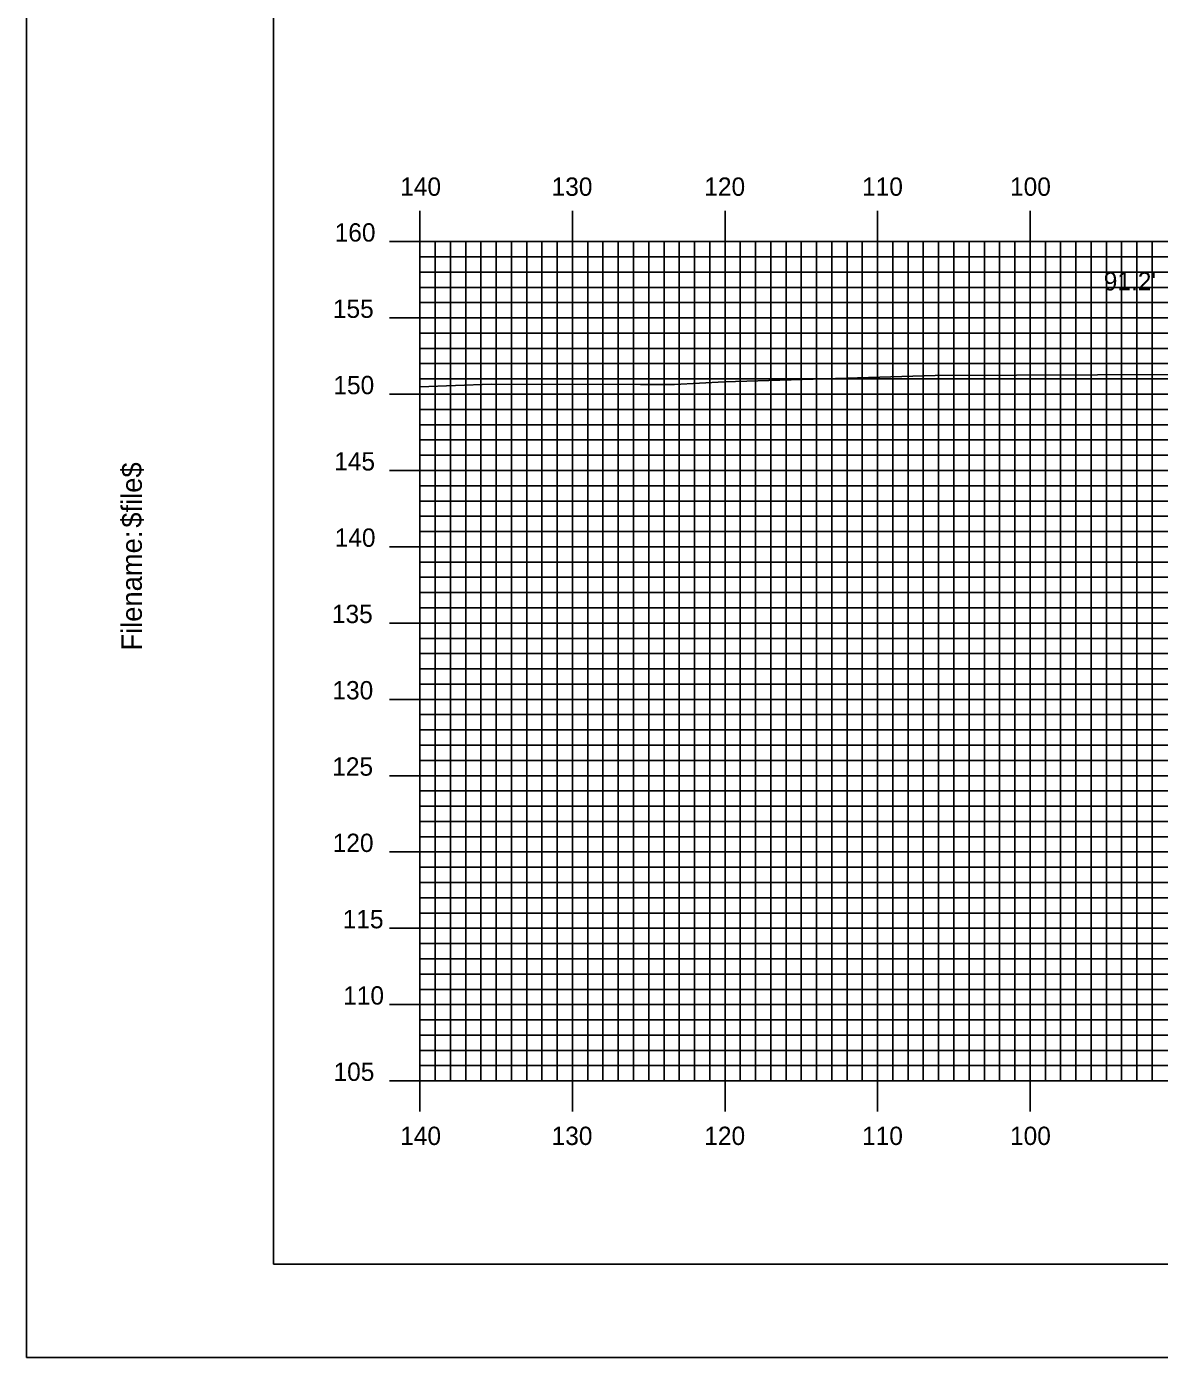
# Model space of a CAD drawing. Extents: x 1770055 to 1770398, y 442591 to 442811.
# Drawn here: x 1770054.7 to 1770129, y 442590.5 to 442677.8 of the extents above; entities that cross this region are included whole.
import ezdxf

# ---------------------------------------------------------------- set-up
doc = ezdxf.new("R2010")
doc.units = 0
for name, color, linetype in [('BORDER', 7, 'Continuous'), ('D_Text_Standard', 7, 'Continuous'), ('H_V ANNOTATION', 7, 'Continuous'), ('MAJOR', 7, 'Continuous'), ('MINOR', 7, 'Continuous'), ('PLOT BOUNDARY', 7, 'Continuous'), ('S_Roadway_Centerline', 7, 'Continuous')]:
    doc.layers.add(name, color=color, linetype=linetype)

msp = doc.modelspace()

# ---------------------------------------------------------------- linework, layer by layer
at = {"layer": 'BORDER'}
msp.add_lwpolyline([(1770070.928, 442596.665), (1770390.928, 442596.665), (1770390.928, 442806.665), (1770070.928, 442806.665)], close=True, dxfattribs=at)
at = {"layer": 'MAJOR'}
for p, q in [((1770080.528, 442665.669), (1770080.528, 442663.665)), ((1770090.528, 442665.669), (1770090.528, 442663.665)), ((1770100.528, 442665.669), (1770100.528, 442663.665)), ((1770110.528, 442665.669), (1770110.528, 442663.665)), ((1770120.528, 442665.669), (1770120.528, 442663.665)), ((1770078.524, 442663.665), (1770080.528, 442663.665)), ((1770080.528, 442663.665), (1770360.528, 442663.665)), ((1770080.528, 442608.665), (1770080.528, 442663.665)), ((1770080.528, 442608.665), (1770080.528, 442663.665)), ((1770080.528, 442663.665), (1770360.528, 442663.665)), ((1770090.528, 442608.665), (1770090.528, 442663.665)), ((1770100.528, 442608.665), (1770100.528, 442663.665)), ((1770110.528, 442608.665), (1770110.528, 442663.665)), ((1770120.528, 442608.665), (1770120.528, 442663.665)), ((1770078.524, 442658.665), (1770080.528, 442658.665)), ((1770080.528, 442658.665), (1770360.528, 442658.665)), ((1770078.524, 442653.665), (1770080.528, 442653.665)), ((1770080.528, 442653.665), (1770360.528, 442653.665)), ((1770078.524, 442648.665), (1770080.528, 442648.665)), ((1770080.528, 442648.665), (1770360.528, 442648.665)), ((1770078.524, 442643.665), (1770080.528, 442643.665)), ((1770080.528, 442643.665), (1770360.528, 442643.665)), ((1770078.524, 442638.665), (1770080.528, 442638.665)), ((1770080.528, 442638.665), (1770360.528, 442638.665)), ((1770078.524, 442633.665), (1770080.528, 442633.665)), ((1770080.528, 442633.665), (1770360.528, 442633.665)), ((1770078.524, 442628.665), (1770080.528, 442628.665)), ((1770080.528, 442628.665), (1770360.528, 442628.665)), ((1770078.524, 442623.665), (1770080.528, 442623.665)), ((1770080.528, 442623.665), (1770360.528, 442623.665)), ((1770078.524, 442618.665), (1770080.528, 442618.665)), ((1770080.528, 442618.665), (1770360.528, 442618.665)), ((1770078.524, 442613.665), (1770080.528, 442613.665)), ((1770080.528, 442613.665), (1770360.528, 442613.665)), ((1770078.524, 442608.665), (1770080.528, 442608.665)), ((1770080.528, 442608.665), (1770360.528, 442608.665)), ((1770080.528, 442608.665), (1770360.528, 442608.665)), ((1770080.528, 442606.661), (1770080.528, 442608.665)), ((1770090.528, 442606.661), (1770090.528, 442608.665)), ((1770100.528, 442606.661), (1770100.528, 442608.665)), ((1770110.528, 442606.661), (1770110.528, 442608.665)), ((1770120.528, 442606.661), (1770120.528, 442608.665))]:
    msp.add_line(p, q, dxfattribs=at)
at = {"layer": 'MINOR'}
for p, q in [((1770081.528, 442608.665), (1770081.528, 442663.665)), ((1770082.528, 442608.665), (1770082.528, 442663.665)), ((1770083.528, 442608.665), (1770083.528, 442663.665)), ((1770084.528, 442608.665), (1770084.528, 442663.665)), ((1770085.528, 442608.665), (1770085.528, 442663.665)), ((1770086.528, 442608.665), (1770086.528, 442663.665)), ((1770087.528, 442608.665), (1770087.528, 442663.665)), ((1770088.528, 442608.665), (1770088.528, 442663.665)), ((1770089.528, 442608.665), (1770089.528, 442663.665)), ((1770091.528, 442608.665), (1770091.528, 442663.665)), ((1770092.528, 442608.665), (1770092.528, 442663.665)), ((1770093.528, 442608.665), (1770093.528, 442663.665)), ((1770094.528, 442608.665), (1770094.528, 442663.665)), ((1770095.528, 442608.665), (1770095.528, 442663.665)), ((1770096.528, 442608.665), (1770096.528, 442663.665)), ((1770097.528, 442608.665), (1770097.528, 442663.665)), ((1770098.528, 442608.665), (1770098.528, 442663.665)), ((1770099.528, 442608.665), (1770099.528, 442663.665)), ((1770101.528, 442608.665), (1770101.528, 442663.665)), ((1770102.528, 442608.665), (1770102.528, 442663.665)), ((1770103.528, 442608.665), (1770103.528, 442663.665)), ((1770104.528, 442608.665), (1770104.528, 442663.665)), ((1770105.528, 442608.665), (1770105.528, 442663.665)), ((1770106.528, 442608.665), (1770106.528, 442663.665)), ((1770107.528, 442608.665), (1770107.528, 442663.665)), ((1770108.528, 442608.665), (1770108.528, 442663.665)), ((1770109.528, 442608.665), (1770109.528, 442663.665)), ((1770111.528, 442608.665), (1770111.528, 442663.665)), ((1770112.528, 442608.665), (1770112.528, 442663.665)), ((1770113.528, 442608.665), (1770113.528, 442663.665)), ((1770114.528, 442608.665), (1770114.528, 442663.665)), ((1770115.528, 442608.665), (1770115.528, 442663.665)), ((1770116.528, 442608.665), (1770116.528, 442663.665)), ((1770117.528, 442608.665), (1770117.528, 442663.665)), ((1770118.528, 442608.665), (1770118.528, 442663.665)), ((1770119.528, 442608.665), (1770119.528, 442663.665)), ((1770121.528, 442608.665), (1770121.528, 442663.665)), ((1770122.528, 442608.665), (1770122.528, 442663.665)), ((1770123.528, 442608.665), (1770123.528, 442663.665)), ((1770124.528, 442608.665), (1770124.528, 442663.665)), ((1770125.528, 442608.665), (1770125.528, 442663.665)), ((1770126.528, 442608.665), (1770126.528, 442663.665)), ((1770127.528, 442608.665), (1770127.528, 442663.665)), ((1770128.528, 442608.665), (1770128.528, 442663.665)), ((1770080.528, 442662.665), (1770360.528, 442662.665)), ((1770080.528, 442662.665), (1770082.532, 442662.665)), ((1770080.528, 442661.665), (1770360.528, 442661.665)), ((1770080.528, 442661.665), (1770082.532, 442661.665)), ((1770080.528, 442660.665), (1770360.528, 442660.665)), ((1770080.528, 442660.665), (1770082.532, 442660.665)), ((1770080.528, 442659.665), (1770360.528, 442659.665)), ((1770080.528, 442659.665), (1770082.532, 442659.665)), ((1770080.528, 442657.665), (1770360.528, 442657.665)), ((1770080.528, 442657.665), (1770082.532, 442657.665)), ((1770080.528, 442656.665), (1770360.528, 442656.665)), ((1770080.528, 442656.665), (1770082.532, 442656.665)), ((1770080.528, 442655.665), (1770360.528, 442655.665)), ((1770080.528, 442655.665), (1770082.532, 442655.665)), ((1770080.528, 442654.665), (1770360.528, 442654.665)), ((1770080.528, 442654.665), (1770082.532, 442654.665)), ((1770080.528, 442652.665), (1770360.528, 442652.665)), ((1770080.528, 442652.665), (1770082.532, 442652.665)), ((1770080.528, 442651.665), (1770360.528, 442651.665)), ((1770080.528, 442651.665), (1770082.532, 442651.665)), ((1770080.528, 442650.665), (1770360.528, 442650.665)), ((1770080.528, 442650.665), (1770082.532, 442650.665)), ((1770080.528, 442649.665), (1770360.528, 442649.665)), ((1770080.528, 442649.665), (1770082.532, 442649.665)), ((1770080.528, 442647.665), (1770360.528, 442647.665)), ((1770080.528, 442647.665), (1770082.532, 442647.665)), ((1770080.528, 442646.665), (1770360.528, 442646.665)), ((1770080.528, 442646.665), (1770082.532, 442646.665)), ((1770080.528, 442645.665), (1770360.528, 442645.665)), ((1770080.528, 442645.665), (1770082.532, 442645.665)), ((1770080.528, 442644.665), (1770360.528, 442644.665)), ((1770080.528, 442644.665), (1770082.532, 442644.665)), ((1770080.528, 442642.665), (1770360.528, 442642.665)), ((1770080.528, 442642.665), (1770082.532, 442642.665)), ((1770080.528, 442641.665), (1770360.528, 442641.665)), ((1770080.528, 442641.665), (1770082.532, 442641.665)), ((1770080.528, 442640.665), (1770360.528, 442640.665)), ((1770080.528, 442640.665), (1770082.532, 442640.665)), ((1770080.528, 442639.665), (1770360.528, 442639.665)), ((1770080.528, 442639.665), (1770082.532, 442639.665)), ((1770080.528, 442637.665), (1770360.528, 442637.665)), ((1770080.528, 442637.665), (1770082.532, 442637.665)), ((1770080.528, 442636.665), (1770360.528, 442636.665)), ((1770080.528, 442636.665), (1770082.532, 442636.665)), ((1770080.528, 442635.665), (1770360.528, 442635.665)), ((1770080.528, 442635.665), (1770082.532, 442635.665)), ((1770080.528, 442634.665), (1770360.528, 442634.665)), ((1770080.528, 442634.665), (1770082.532, 442634.665)), ((1770080.528, 442632.665), (1770360.528, 442632.665)), ((1770080.528, 442632.665), (1770082.532, 442632.665)), ((1770080.528, 442631.665), (1770360.528, 442631.665)), ((1770080.528, 442631.665), (1770082.532, 442631.665)), ((1770080.528, 442630.665), (1770360.528, 442630.665)), ((1770080.528, 442630.665), (1770082.532, 442630.665)), ((1770080.528, 442629.665), (1770360.528, 442629.665)), ((1770080.528, 442629.665), (1770082.532, 442629.665)), ((1770080.528, 442627.665), (1770360.528, 442627.665)), ((1770080.528, 442627.665), (1770082.532, 442627.665)), ((1770080.528, 442626.665), (1770360.528, 442626.665)), ((1770080.528, 442626.665), (1770082.532, 442626.665)), ((1770080.528, 442625.665), (1770360.528, 442625.665)), ((1770080.528, 442625.665), (1770082.532, 442625.665)), ((1770080.528, 442624.665), (1770360.528, 442624.665)), ((1770080.528, 442624.665), (1770082.532, 442624.665)), ((1770080.528, 442622.665), (1770360.528, 442622.665)), ((1770080.528, 442622.665), (1770082.532, 442622.665)), ((1770080.528, 442621.665), (1770360.528, 442621.665)), ((1770080.528, 442621.665), (1770082.532, 442621.665)), ((1770080.528, 442620.665), (1770360.528, 442620.665)), ((1770080.528, 442620.665), (1770082.532, 442620.665)), ((1770080.528, 442619.665), (1770360.528, 442619.665)), ((1770080.528, 442619.665), (1770082.532, 442619.665)), ((1770080.528, 442617.665), (1770360.528, 442617.665)), ((1770080.528, 442617.665), (1770082.532, 442617.665)), ((1770080.528, 442616.665), (1770360.528, 442616.665)), ((1770080.528, 442616.665), (1770082.532, 442616.665)), ((1770080.528, 442615.665), (1770360.528, 442615.665)), ((1770080.528, 442615.665), (1770082.532, 442615.665)), ((1770080.528, 442614.665), (1770360.528, 442614.665)), ((1770080.528, 442614.665), (1770082.532, 442614.665)), ((1770080.528, 442612.665), (1770360.528, 442612.665)), ((1770080.528, 442612.665), (1770082.532, 442612.665)), ((1770080.528, 442611.665), (1770360.528, 442611.665)), ((1770080.528, 442611.665), (1770082.532, 442611.665)), ((1770080.528, 442610.665), (1770360.528, 442610.665)), ((1770080.528, 442610.665), (1770082.532, 442610.665)), ((1770080.528, 442609.665), (1770360.528, 442609.665)), ((1770080.528, 442609.665), (1770082.532, 442609.665))]:
    msp.add_line(p, q, dxfattribs=at)
at = {"layer": 'PLOT BOUNDARY'}
msp.add_lwpolyline([(1770054.741, 442590.547), (1770394.741, 442590.547), (1770394.741, 442810.547), (1770054.741, 442810.547)], close=True, dxfattribs=at)
at = {"layer": 'S_Roadway_Centerline'}
msp.add_lwpolyline([(1770080.528, 442654.157), (1770085.186, 442654.318), (1770094.979, 442654.295), (1770097.217, 442654.304), (1770100.488, 442654.483), (1770114.303, 442654.9), (1770130.273, 442654.953), (1770131.884, 442654.971), (1770133.085, 442655.012), (1770144.868, 442655.54), (1770153.558, 442655.315), (1770162.971, 442655.45), (1770171.758, 442655.657), (1770179.977, 442655.201), (1770191.894, 442655.367), (1770192.415, 442655.364), (1770199.74, 442655.199), (1770205.48, 442654.814), (1770211.859, 442654.469), (1770223.576, 442654.243), (1770230.798, 442654.178), (1770247.848, 442652.967), (1770251.575, 442652.677)], dxfattribs=at)

# ---------------------------------------------------------------- texts
at = {"layer": 'BORDER'}
for s, p in [('$file$', (1770062.298, 442644.916)), ('Filename:', (1770062.298, 442636.862))]:
    msp.add_text(s, height=1.3392, rotation=90, dxfattribs=at).set_placement(p)
at = {"layer": 'D_Text_Standard'}
msp.add_text("91.2'", height=1.2, dxfattribs=at).set_placement((1770125.356, 442660.464))
at = {"layer": 'H_V ANNOTATION'}
for s, p in [('140', (1770079.233, 442666.665)), ('130', (1770089.158, 442666.665)), ('120', (1770099.169, 442666.665)), ('110', (1770109.511, 442666.665)), ('100', (1770119.211, 442666.665)), ('160', (1770074.938, 442663.665)), ('155', (1770074.82, 442658.665)), ('150', (1770074.852, 442653.665)), ('145', (1770074.906, 442648.665)), ('140', (1770074.938, 442643.665)), ('135', (1770074.756, 442638.665)), ('130', (1770074.788, 442633.665)), ('125', (1770074.777, 442628.665)), ('120', (1770074.809, 442623.665)), ('115', (1770075.463, 442618.665)), ('110', (1770075.495, 442613.665)), ('105', (1770074.863, 442608.665)), ('140', (1770079.233, 442604.465)), ('130', (1770089.158, 442604.465)), ('120', (1770099.169, 442604.465)), ('110', (1770109.511, 442604.465)), ('100', (1770119.211, 442604.465))]:
    msp.add_text(s, height=1.2, dxfattribs=at).set_placement(p)
at = {"layer": 'MAJOR'}
msp.add_text('-', height=0.012, dxfattribs=at).set_placement((1770080.519, 442608.665))

doc.saveas('drawing.dxf')
